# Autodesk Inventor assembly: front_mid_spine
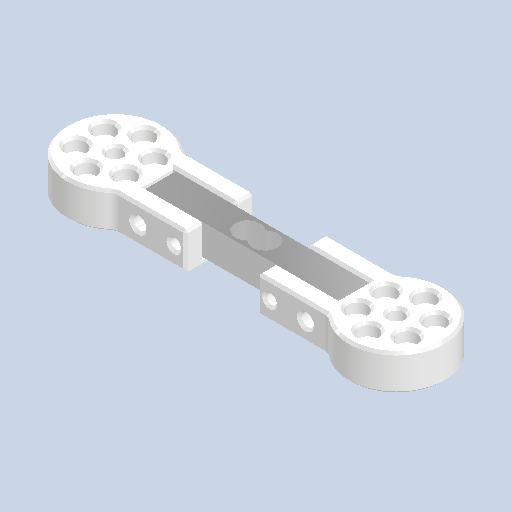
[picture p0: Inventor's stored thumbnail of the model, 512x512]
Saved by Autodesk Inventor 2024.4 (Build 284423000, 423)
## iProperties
Created: 2026-01
Part Number: front_mid_spine
Document SubType Name: Assembly
Designer: AdminForWorker
Title: front_mid_spine v1
Author: AdminForWorker
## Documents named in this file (3)
- c:\worker\convert-fusion-r06-cosv3\tmp\job-1\16\temp\files\783ac935-f7b1-476b-a693-59a41befcd46\91199a33-6f70-44f6-878f-b511bc50f34f.iam
- c:\worker\convert-fusion-r06-cosv3\tmp\job-1\16\temp\files\783ac935-f7b1-476b-a693-59a41befcd46\Xiaomi_spine2-1.ipt
- c:\worker\convert-fusion-r06-cosv3\tmp\job-1\16\temp\files\783ac935-f7b1-476b-a693-59a41befcd46\load_cell.ipt
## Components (2 placed, 2 different names)
1. Xiaomi_spine2-1:1
2. load_cell:1
